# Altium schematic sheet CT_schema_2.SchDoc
size 276 x 169 mm
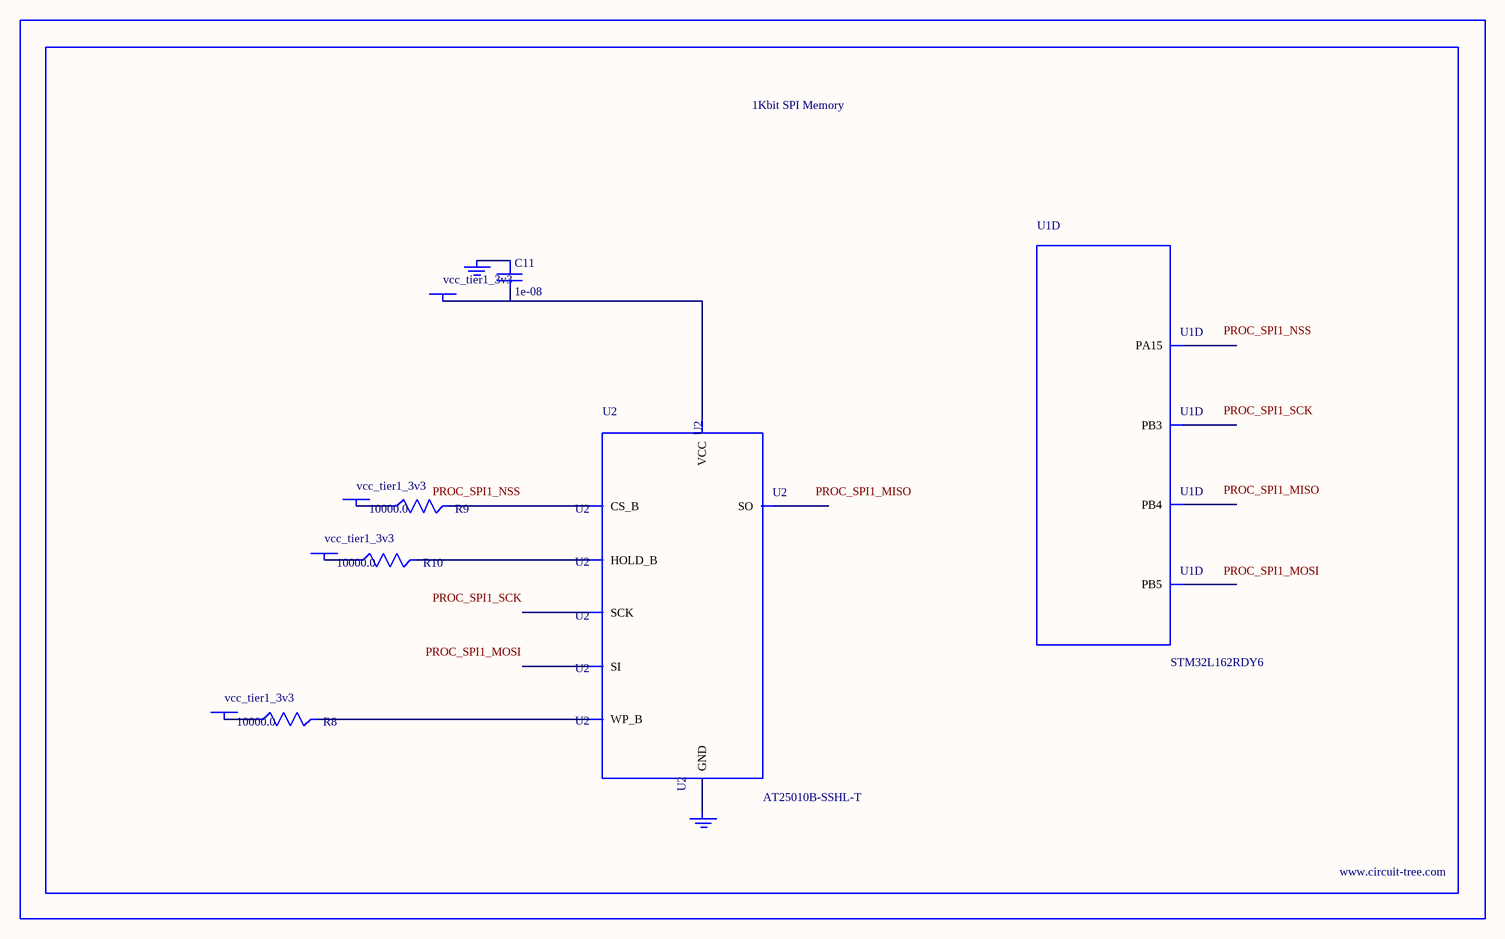
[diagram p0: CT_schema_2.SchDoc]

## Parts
BORDER1  (no value)
C11  1e-08  [C0402]
GND_INSTANCE_1_0  (no value)
GND_INSTANCE_1_1  (no value)
POWER_INSTANCE_1_0  vcc_tier1_3v3
POWER_INSTANCE_1_1  vcc_tier1_3v3
POWER_INSTANCE_1_2  vcc_tier1_3v3
POWER_INSTANCE_1_3  vcc_tier1_3v3
R8  10000.0  [R0603]
R9  10000.0  [R0603]
R10  10000.0  [R0603]
U1  STM32L162RDY6  [WLCSP64]  (part D of 6)
U2  AT25010B-SSHL-T  [SOIC-8]

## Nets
NetC11_1: C11.1 GND_INSTANCE_1_0.0(GND)
NetC11_2: C11.2 POWER_INSTANCE_1_3.0(PWR) U2.8(VCC)
NetGND_INSTANCE_1_1_0: GND_INSTANCE_1_1.0(GND) U2.4(GND)
NetPOWER_INSTANCE_1_0_0: POWER_INSTANCE_1_0.0(PWR) R9.1
NetPOWER_INSTANCE_1_1_0: POWER_INSTANCE_1_1.0(PWR) R8.1
NetPOWER_INSTANCE_1_2_0: POWER_INSTANCE_1_2.0(PWR) R10.1
NetR8_2: R8.2 U2.3(WP_B)
NetR9_2: R9.2 U2.1(CS_B)
NetR10_2: R10.2 U2.7(HOLD_B)

Not connected (* = marked no-connect by the designer): U1 A4(PB3) A5(PB5) B4(PB4) C3(PA15); U2 2(SO) 5(SI) 6(SCK)

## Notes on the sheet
- Labels drawn without touching a wire or pin: PROC_SPI1_MISO, PROC_SPI1_MOSI, PROC_SPI1_NSS, PROC_SPI1_SCK

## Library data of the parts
BORDER1 = BORDER_PAGE1
C11 = C0402C103K3RAC
GND_INSTANCE_1_0 GND_INSTANCE_1_1 = GND
POWER_INSTANCE_1_0-POWER_INSTANCE_1_3 = PWR
R8-R10 = RC0603JR-0710KL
